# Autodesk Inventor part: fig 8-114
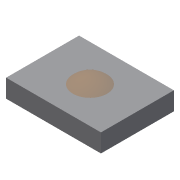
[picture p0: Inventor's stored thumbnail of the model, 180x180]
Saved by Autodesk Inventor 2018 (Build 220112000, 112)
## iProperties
Created: 2009-09
Part Number: fig 8-114
Document SubType Name: Modeling
Designer: Sham
Density: 1 g/cm^3
Material: Generic
Appearance: Default
Author: Sham
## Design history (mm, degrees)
sketch "Sketch1"
  geometry: L1 (-26, 20)-(0, 20); L2 (0, 20)-(0, 0); L3 (0, 0)-(-26, 0); L4 (-26, 0)-(-26, 20)
  constraints: 8 end point, 2 parallel, 1 horizontal, 1 perpendicular
extrude "Extrusion1" new body sketch "Sketch1" distance "d0" = 5; taper "d1" = 0 deg
workplane "Work Plane1"
sketch "Sketch2"
  geometry: L1 (13, 8)-(13, 5); A1 r 7.517 centre (12.377, -0.349) between (17.658, 5) and (13, 7.142)
  constraints: 2 end point, 2 point on circle, 1 centre point
feature "RevolutionSrf2" sketch "Sketch2" dims angle "d4" = 90 deg
body "Solid1"
body "Srf2"
